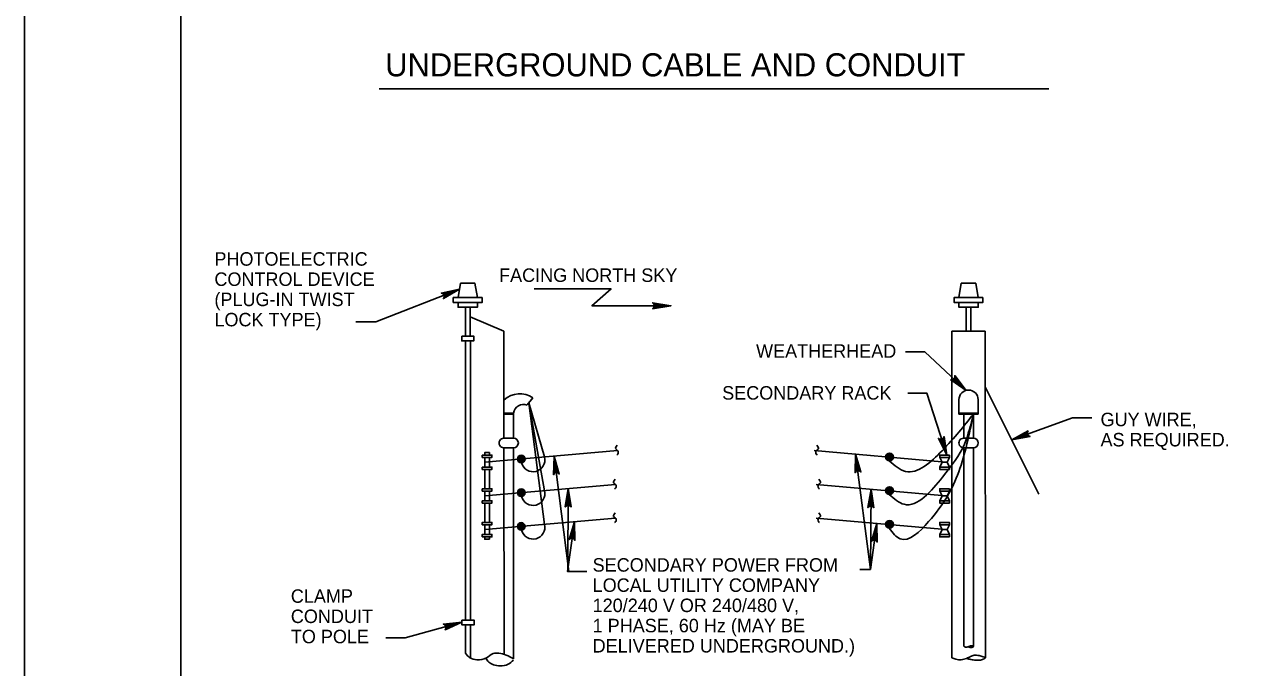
# Model space of a CAD drawing. Extents: x 638448 to 639352, y 297825 to 299013.
# Drawn here: x 638447.7 to 638752, y 298691.2 to 298851.5 of the extents above; entities that cross this region are included whole.
import ezdxf

# ---------------------------------------------------------------- set-up
doc = ezdxf.new("R2010")
doc.units = 0
for name, color, linetype in [('1', 7, 'Continuous'), ('2', 7, 'Continuous'), ('3', 7, 'Continuous'), ('PLT-BNDY', 7, 'Continuous')]:
    doc.layers.add(name, color=color, linetype=linetype)

msp = doc.modelspace()

# ---------------------------------------------------------------- linework, layer by layer
at = {"layer": '1'}
msp.add_lwpolyline([(639272.65, 298434.29), (639272.65, 298998.29), (638486.65, 298998.29), (638486.65, 298434.29), (639272.65, 298434.29), (639272.65, 298460.65), (639072.65, 298460.65), (639072.65, 298525.33), (639272.65, 298525.33), (639272.65, 298554.29), (639072.65, 298554.29), (639072.65, 298434.29), (639151.45, 298434.29), (639151.45, 298460.65), (639151.45, 298434.29), (639228.45, 298434.29), (639228.45, 298460.65), (639228.45, 298448.33), (639272.65, 298448.33)], dxfattribs=at)
at = {"layer": '2'}
for p, q in [((638535.24, 298777.34), (638556.11, 298785.48)), ((638530.28, 298777.34), (638535.24, 298777.34)), ((638567.16, 298774.99), (638558.76, 298778.59)), ((638567.16, 298774.99), (638567.17, 298748.35)), ((638687.16, 298774.99), (638678.82, 298774.99)), ((638687.16, 298774.99), (638687.2, 298693.57)), ((638687.17, 298761.18), (638700.53, 298734.39)), ((638572.95, 298756.62), (638574.38, 298758.44)), ((638680.59, 298754.35), (638680.59, 298757.95)), ((638685.39, 298754.35), (638685.39, 298757.95)), ((638577.31, 298743.66), (638573.36, 298757.14)), ((638577.31, 298735.26), (638573.36, 298757.14)), ((638573.36, 298757.14), (638577.31, 298726.86)), ((638569.57, 298754.59), (638567.17, 298754.59)), ((638569.57, 298754.35), (638567.17, 298754.35)), ((638569.57, 298754.59), (638569.57, 298748.35)), ((638685.39, 298754.59), (638680.59, 298754.59)), ((638685.39, 298754.35), (638680.59, 298754.35)), ((638681.79, 298754.35), (638681.79, 298748.35)), ((638684.19, 298754.35), (638684.19, 298748.35)), ((638569.57, 298748.35), (638567.17, 298748.35)), ((638569.57, 298745.95), (638567.17, 298745.95)), ((638567.18, 298745.95), (638567.18, 298745.95)), ((638567.18, 298745.95), (638567.2, 298694.36)), ((638569.58, 298745.95), (638569.6, 298693.31)), ((638684.19, 298748.35), (638681.79, 298748.35)), ((638684.19, 298745.95), (638681.79, 298745.95)), ((638681.8, 298745.95), (638681.82, 298696.48)), ((638684.2, 298745.95), (638684.22, 298696.48)), ((638687.18, 298745.95), (638687.18, 298745.95)), ((638562.38, 298742.35), (638595.49, 298745.25)), ((638563.58, 298744.75), (638563.58, 298744.75)), ((638571.46, 298742.37), (638570.7, 298743.18)), ((638570.7, 298743.18), (638571.96, 298742.41)), ((638572.11, 298743.35), (638570.72, 298742.96)), ((638570.72, 298742.96), (638572.29, 298743.15)), ((638571.83, 298743.78), (638570.76, 298743.31)), ((638570.76, 298743.31), (638572.11, 298743.35)), ((638570.93, 298743.7), (638571.83, 298743.78)), ((638572.29, 298743.15), (638570.93, 298742.6)), ((638570.93, 298742.6), (638572.22, 298742.74)), ((638571.96, 298742.41), (638571.28, 298743.93)), ((638571.28, 298743.93), (638572.33, 298742.99)), ((638572.22, 298742.74), (638571.46, 298742.37)), ((638571.5, 298743.15), (638571.5, 298743.15)), ((638572.33, 298742.99), (638571.96, 298743.89)), ((638676.37, 298742.46), (638644.5, 298745.25)), ((638663.51, 298744.44), (638662.47, 298743.5)), ((638662.47, 298743.5), (638662.83, 298744.4)), ((638664.07, 298743.46), (638662.5, 298743.66)), ((638662.5, 298743.66), (638663.87, 298743.11)), ((638663.87, 298743.11), (638662.57, 298743.25)), ((638662.57, 298743.25), (638663.34, 298742.87)), ((638664.04, 298743.81), (638662.68, 298743.86)), ((638662.68, 298743.86), (638664.07, 298743.46)), ((638662.83, 298742.92), (638663.51, 298744.44)), ((638664.09, 298743.68), (638662.83, 298742.92)), ((638663.87, 298744.21), (638662.97, 298744.28)), ((638662.97, 298744.28), (638664.04, 298743.81)), ((638663.29, 298743.66), (638663.29, 298743.66)), ((638663.34, 298742.87), (638664.09, 298743.68)), ((638675.82, 298743.55), (638676.42, 298742.35)), ((638677.62, 298742.35), (638678.22, 298743.55)), ((638676.42, 298742.35), (638675.82, 298741.15)), ((638676.42, 298742.35), (638677.62, 298742.35)), ((638678.22, 298741.15), (638677.62, 298742.35)), ((638562.38, 298733.95), (638594.97, 298736.8)), ((638676.37, 298734.06), (638645.02, 298736.8)), ((638571.46, 298733.97), (638570.7, 298734.78)), ((638570.7, 298734.78), (638571.96, 298734.01)), ((638572.11, 298734.95), (638570.72, 298734.56)), ((638570.72, 298734.56), (638572.29, 298734.75)), ((638571.83, 298735.38), (638570.76, 298734.91)), ((638570.76, 298734.91), (638572.11, 298734.95)), ((638570.93, 298735.3), (638571.83, 298735.38)), ((638572.29, 298734.75), (638570.93, 298734.2)), ((638570.93, 298734.2), (638572.22, 298734.34)), ((638571.96, 298734.01), (638571.28, 298735.53)), ((638571.28, 298735.53), (638572.33, 298734.59)), ((638572.22, 298734.34), (638571.46, 298733.97)), ((638571.5, 298734.75), (638571.5, 298734.75)), ((638572.33, 298734.59), (638571.96, 298735.49)), ((638663.51, 298736.04), (638662.47, 298735.1)), ((638662.47, 298735.1), (638662.83, 298736)), ((638664.07, 298735.06), (638662.5, 298735.26)), ((638662.5, 298735.26), (638663.87, 298734.71)), ((638663.87, 298734.71), (638662.57, 298734.85)), ((638662.57, 298734.85), (638663.34, 298734.47)), ((638664.04, 298735.41), (638662.68, 298735.46)), ((638662.68, 298735.46), (638664.07, 298735.06)), ((638662.83, 298734.52), (638663.51, 298736.04)), ((638664.09, 298735.28), (638662.83, 298734.52)), ((638663.87, 298735.81), (638662.97, 298735.88)), ((638662.97, 298735.88), (638664.04, 298735.41)), ((638663.29, 298735.26), (638663.29, 298735.26)), ((638663.34, 298734.47), (638664.09, 298735.28)), ((638675.82, 298735.15), (638676.42, 298733.95)), ((638676.42, 298733.95), (638675.82, 298732.75)), ((638676.42, 298733.95), (638677.62, 298733.95)), ((638677.62, 298733.95), (638678.22, 298735.15)), ((638678.22, 298732.75), (638677.62, 298733.95)), ((638562.38, 298725.55), (638594.97, 298728.4)), ((638676.37, 298725.66), (638645.02, 298728.4)), ((638663.51, 298727.64), (638662.47, 298726.7)), ((638662.47, 298726.7), (638662.83, 298727.6)), ((638662.83, 298726.12), (638663.51, 298727.64)), ((638663.87, 298727.41), (638662.97, 298727.48)), ((638662.97, 298727.48), (638664.04, 298727.01)), ((638571.46, 298725.57), (638570.7, 298726.38)), ((638570.7, 298726.38), (638571.96, 298725.61)), ((638572.11, 298726.55), (638570.72, 298726.16)), ((638570.72, 298726.16), (638572.29, 298726.35)), ((638571.83, 298726.98), (638570.76, 298726.51)), ((638570.76, 298726.51), (638572.11, 298726.55)), ((638570.93, 298726.9), (638571.83, 298726.98)), ((638572.29, 298726.35), (638570.93, 298725.8)), ((638570.93, 298725.8), (638572.22, 298725.94)), ((638571.96, 298725.61), (638571.28, 298727.13)), ((638571.28, 298727.13), (638572.33, 298726.19)), ((638572.22, 298725.94), (638571.46, 298725.57)), ((638571.5, 298726.35), (638571.5, 298726.35)), ((638572.33, 298726.19), (638571.96, 298727.09)), ((638664.07, 298726.66), (638662.5, 298726.86)), ((638662.5, 298726.86), (638663.87, 298726.31)), ((638663.87, 298726.31), (638662.57, 298726.45)), ((638662.57, 298726.45), (638663.34, 298726.07)), ((638664.04, 298727.01), (638662.68, 298727.06)), ((638662.68, 298727.06), (638664.07, 298726.66)), ((638664.09, 298726.88), (638662.83, 298726.12)), ((638663.29, 298726.86), (638663.29, 298726.86)), ((638663.34, 298726.07), (638664.09, 298726.88)), ((638675.82, 298726.75), (638676.42, 298725.55)), ((638676.42, 298725.55), (638675.82, 298724.35)), ((638676.42, 298725.55), (638677.62, 298725.55)), ((638677.62, 298725.55), (638678.22, 298726.75)), ((638678.22, 298724.35), (638677.62, 298725.55)), ((638563.58, 298723.15), (638563.58, 298723.15))]:
    msp.add_line(p, q, dxfattribs=at)
for points in [[(638551.85, 298784.41), (638552.11, 298784.18), (638556.11, 298785.48), (638551.85, 298784.41), (638551.57, 298784.51), (638556.11, 298785.48), (638552.28, 298783.77), (638552.25, 298783.42), (638556.11, 298785.48), (638552.1, 298783.14), (638552.25, 298783.42)], [(638555.76, 298783.39), (638556.36, 298786.99), (638559.96, 298786.99), (638560.56, 298783.39), (638561.76, 298783.39)], [(638608.81, 298781.36), (638589.1, 298781.36), (638593.88, 298785.56), (638584.28, 298785.56), (638574.68, 298785.56)], [(638680.59, 298783.39), (638681.19, 298786.99), (638684.79, 298786.99), (638685.39, 298783.39), (638686.59, 298783.39)], [(638604.45, 298781.91), (638604.61, 298781.59), (638608.81, 298781.36), (638604.45, 298781.91), (638604.22, 298782.1), (638608.81, 298781.36), (638604.61, 298781.15), (638604.46, 298780.84), (638608.81, 298781.36), (638604.22, 298780.63), (638604.46, 298780.84)], [(638682.39, 298774.94), (638682.39, 298780.99), (638683.59, 298780.99)], [(638683.59, 298780.99), (638683.59, 298774.99)], [(638678.82, 298774.99), (638678.82, 298693.57)], [(638667.26, 298769.89), (638672.06, 298769.89), (638682.39, 298760.27)], [(638679.57, 298763.65), (638679.48, 298763.3), (638682.39, 298760.27), (638679.57, 298763.65), (638679.54, 298763.94), (638682.39, 298760.27), (638679.18, 298762.98), (638678.85, 298762.86), (638682.39, 298760.27), (638678.54, 298762.86), (638678.85, 298762.86)], [(638667.82, 298759.55), (638672.62, 298759.55), (638677.61, 298744.15)], [(638713.68, 298753.39), (638708.88, 298753.39), (638693.78, 298747.91)], [(638698.07, 298748.89), (638697.81, 298749.13), (638693.78, 298747.91), (638698.07, 298748.89), (638698.34, 298748.78), (638693.78, 298747.91), (638697.65, 298749.54), (638697.69, 298749.89), (638693.78, 298747.91), (638697.84, 298750.16), (638697.69, 298749.89)], [(638676.78, 298748.47), (638676.53, 298748.22), (638677.61, 298744.15), (638676.78, 298748.47), (638676.9, 298748.74), (638677.61, 298744.15), (638676.12, 298748.08), (638675.77, 298748.13), (638677.61, 298744.15), (638675.5, 298748.29), (638675.77, 298748.13)], [(638579.68, 298739.47), (638579.97, 298739.67), (638579.67, 298743.87), (638579.68, 298739.47), (638579.52, 298739.23), (638579.67, 298743.87), (638580.41, 298739.73), (638580.74, 298739.62), (638579.67, 298743.87), (638580.98, 298739.41), (638580.74, 298739.62)], [(638583.35, 298715.08), (638579.67, 298743.87)], [(638654.86, 298739.98), (638655.15, 298740.18), (638654.85, 298744.38), (638654.86, 298739.98), (638654.7, 298739.74), (638654.85, 298744.38), (638655.59, 298740.24), (638655.92, 298740.13), (638654.85, 298744.38), (638656.15, 298739.92), (638655.92, 298740.13)], [(638658.53, 298715.59), (638654.85, 298744.38)], [(638582.65, 298731.42), (638582.97, 298731.58), (638583.23, 298735.78), (638582.65, 298731.42), (638582.46, 298731.2), (638583.23, 298735.78), (638583.41, 298731.58), (638583.72, 298731.43), (638583.23, 298735.78), (638583.93, 298731.19), (638583.72, 298731.43)], [(638583.08, 298715.08), (638583.23, 298735.78)], [(638658.1, 298731.26), (638658.42, 298731.42), (638658.68, 298735.61), (638658.1, 298731.26), (638657.91, 298731.03), (638658.68, 298735.61), (638658.86, 298731.42), (638659.17, 298731.26), (638658.68, 298735.61), (638659.38, 298731.02), (638659.17, 298731.26)], [(638658.53, 298715.59), (638658.68, 298735.61)], [(638587.83, 298715.08), (638583.03, 298715.08), (638584.79, 298727.51)], [(638583.64, 298723.27), (638583.97, 298723.39), (638584.79, 298727.51), (638583.64, 298723.27), (638583.42, 298723.08), (638584.79, 298727.51), (638584.41, 298723.33), (638584.7, 298723.14), (638584.79, 298727.51), (638584.87, 298722.87), (638584.7, 298723.14)], [(638658.53, 298715.59), (638660.16, 298727.08)], [(638659.01, 298722.84), (638659.34, 298722.96), (638660.16, 298727.08), (638659.01, 298722.84), (638658.79, 298722.65), (638660.16, 298727.08), (638659.78, 298722.9), (638660.06, 298722.7), (638660.16, 298727.08), (638660.24, 298722.44), (638660.06, 298722.7)], [(638658.53, 298715.59), (638655.86, 298715.59)], [(638537.77, 298698.58), (638542.57, 298698.58), (638556.72, 298702.49)], [(638552.37, 298701.86), (638552.61, 298701.6), (638556.72, 298702.49), (638552.37, 298701.86), (638552.11, 298701.98), (638556.72, 298702.49), (638552.73, 298701.17), (638552.67, 298700.83), (638556.72, 298702.49), (638552.5, 298700.57), (638552.67, 298700.83)], [(638557.62, 298694.75), (638557.62, 298701.79), (638558.82, 298701.79), (638558.82, 298693.6)]]:
    msp.add_lwpolyline(points, dxfattribs=at)
for points in [[(638561.76, 298783.39), (638561.76, 298782.19), (638554.56, 298782.19), (638554.56, 298783.39)], [(638686.59, 298783.39), (638686.59, 298782.19), (638679.39, 298782.19), (638679.39, 298783.39)], [(638555.76, 298782.19), (638555.76, 298780.99), (638560.56, 298780.99), (638560.56, 298782.19)], [(638558.76, 298780.99), (638558.76, 298773.79), (638557.56, 298773.79), (638557.56, 298780.99)], [(638680.59, 298782.19), (638680.59, 298780.99), (638685.39, 298780.99), (638685.39, 298782.19)], [(638556.66, 298773.79), (638556.66, 298772.59), (638559.66, 298772.59), (638559.66, 298773.79)], [(638558.82, 298772.59), (638558.82, 298702.99), (638557.62, 298702.99), (638557.62, 298772.59)], [(638561.78, 298744.15), (638561.78, 298743.55), (638564.18, 298743.55), (638564.18, 298744.15)], [(638563.58, 298744.75), (638563.58, 298744.15), (638562.38, 298744.15), (638562.38, 298744.75)], [(638563.58, 298743.55), (638563.58, 298741.15), (638562.38, 298741.15), (638562.38, 298743.55)], [(638678.22, 298744.15), (638678.22, 298743.55), (638675.82, 298743.55), (638675.82, 298744.15)], [(638561.78, 298741.15), (638561.78, 298740.55), (638564.18, 298740.55), (638564.18, 298741.15)], [(638563.58, 298740.55), (638563.58, 298735.75), (638562.38, 298735.75), (638562.38, 298740.55)], [(638678.22, 298741.15), (638678.22, 298740.55), (638675.82, 298740.55), (638675.82, 298741.15)], [(638561.78, 298735.75), (638561.78, 298735.15), (638564.18, 298735.15), (638564.18, 298735.75)], [(638563.58, 298735.15), (638563.58, 298732.75), (638562.38, 298732.75), (638562.38, 298735.15)], [(638678.22, 298735.75), (638678.22, 298735.15), (638675.82, 298735.15), (638675.82, 298735.75)], [(638561.78, 298732.75), (638561.78, 298732.15), (638564.18, 298732.15), (638564.18, 298732.75)], [(638563.58, 298732.15), (638563.58, 298727.35), (638562.38, 298727.35), (638562.38, 298732.15)], [(638678.22, 298732.75), (638678.22, 298732.15), (638675.82, 298732.15), (638675.82, 298732.75)], [(638561.78, 298726.75), (638561.78, 298727.35), (638564.18, 298727.35), (638564.18, 298726.75)], [(638563.58, 298724.35), (638563.58, 298726.75), (638562.38, 298726.75), (638562.38, 298724.35)], [(638678.22, 298726.75), (638678.22, 298727.35), (638675.82, 298727.35), (638675.82, 298726.75)], [(638561.78, 298723.75), (638561.78, 298724.35), (638564.18, 298724.35), (638564.18, 298723.75)], [(638563.58, 298723.15), (638563.58, 298723.75), (638562.38, 298723.75), (638562.38, 298723.15)], [(638678.22, 298723.75), (638678.22, 298724.35), (638675.82, 298724.35), (638675.82, 298723.75)], [(638556.72, 298702.99), (638556.72, 298701.79), (638559.72, 298701.79), (638559.72, 298702.99)]]:
    msp.add_lwpolyline(points, close=True, dxfattribs=at)
for centre in [(638571.5, 298743.15), (638663.29, 298743.66), (638571.5, 298734.75), (638663.29, 298735.26), (638663.29, 298726.86), (638571.5, 298726.35)]:
    msp.add_circle(centre, 0.96, dxfattribs=at)
for centre, radius, start, end in [((638571.15, 298753.47), 5.93, 56.9427, 131.3756), ((638682.99, 298757.95), 2.4, 0, 180), ((638572.07, 298754.25), 2.52, 69.6112, 172.2289), ((638567.17, 298747.15), 1.2, 90, 270.1833), ((638569.57, 298747.15), 1.2, 270, 90), ((638681.79, 298747.15), 1.2, 90, 270.1833), ((638684.19, 298747.15), 1.2, 270, 90), ((638574.45, 298742.93), 2.95, 194.3606, 14.3606), ((638574.45, 298734.53), 2.95, 194.3606, 14.3606), ((638574.45, 298726.13), 2.95, 194.3606, 14.3606)]:
    msp.add_arc(centre, radius, start, end, dxfattribs=at)
for points in [[(638684.19, 298754.35), (638676.39, 298745.2), (638667.26, 298740.07), (638663.21, 298742.7)], [(638684.19, 298754.35), (638681.95, 298746.87), (638676.5, 298738.66), (638666.94, 298731.86), (638663.21, 298734.3)], [(638684.19, 298754.35), (638680.55, 298739.96), (638673.04, 298727.54), (638665.97, 298723.22), (638663.21, 298725.9)], [(638595.44, 298746.61), (638595.05, 298745.7), (638595.57, 298745.18), (638595.57, 298744.4), (638595.31, 298744.14)], [(638645.16, 298746.61), (638645.55, 298745.7), (638645.03, 298745.18), (638645.03, 298744.4), (638645.29, 298744.14)], [(638594.91, 298738.16), (638594.52, 298737.25), (638595.04, 298736.73), (638595.04, 298735.95), (638594.78, 298735.69)], [(638645.68, 298738.16), (638646.07, 298737.25), (638645.55, 298736.73), (638645.55, 298735.95), (638645.81, 298735.69)], [(638594.91, 298729.76), (638594.52, 298728.85), (638595.04, 298728.33), (638595.04, 298727.55), (638594.78, 298727.29)], [(638645.68, 298729.76), (638646.07, 298728.85), (638645.55, 298728.33), (638645.55, 298727.55), (638645.81, 298727.29)], [(638557.62, 298694.75), (638558.71, 298693.6), (638560.43, 298693.12), (638562.83, 298693.6), (638564.46, 298694.65), (638565.9, 298694.75), (638567.72, 298694.27), (638569.6, 298693.31)], [(638678.82, 298693.57), (638679.82, 298693.23), (638681.18, 298693.11), (638682.44, 298693.46), (638683.47, 298693.89), (638684.38, 298694.21), (638685.61, 298694.14), (638686.67, 298693.84), (638687.2, 298693.57)], [(638681.82, 298696.48), (638682.24, 298696.28), (638682.82, 298696.31), (638683.27, 298696.46), (638683.67, 298696.61), (638684.22, 298696.48)], [(638684.22, 298696.48), (638684.05, 298696.23), (638683.6, 298696.18), (638683.14, 298696.23), (638682.99, 298696.31)], [(638569.6, 298693.02), (638568.2, 298691.97), (638566.28, 298691.58), (638564.56, 298691.87), (638563.4, 298692.54), (638562.64, 298693.5)], [(638687.2, 298693.57), (638686.49, 298693.18), (638685.36, 298692.98), (638684.13, 298693.08), (638683.07, 298693.28), (638682.61, 298693.43)]]:
    msp.add_spline(points, degree=3, dxfattribs=at)
at = {"layer": '3'}
msp.add_line((638536.07, 298835.46), (638702.97, 298835.46), dxfattribs=at)
at = {"layer": 'PLT-BNDY'}
msp.add_lwpolyline([(638447.65, 299013.29), (639288.65, 299013.29), (639288.65, 298419.29), (638447.65, 298419.29)], close=True, dxfattribs=at)

# ---------------------------------------------------------------- texts
at = {"layer": '3'}
for s, height, p in [('UNDERGROUND CABLE AND CONDUIT', 5.76, (638537.59, 298838.55)), ('PHOTOELECTRIC', 3.36, (638495.01, 298791.35)), ('CONTROL DEVICE', 3.36, (638495.01, 298786.31)), ('FACING NORTH SKY', 3.36, (638565.97, 298787.31)), ('(PLUG-IN TWIST', 3.36, (638495.01, 298781.27)), ('LOCK TYPE)', 3.36, (638495.01, 298776.23)), ('WEATHERHEAD', 3.36, (638630.03, 298768.4)), ('SECONDARY RACK', 3.36, (638621.58, 298757.96)), ('GUY WIRE,', 3.36, (638715.89, 298751.33)), ('AS REQUIRED.', 3.36, (638715.89, 298746.29)), ('SECONDARY POWER FROM', 3.36, (638589.29, 298715.07)), ('LOCAL UTILITY COMPANY', 3.36, (638589.29, 298710.03)), ('CLAMP', 3.36, (638514.06, 298707.3)), ('120/240 V OR 240/480 V, ', 3.36, (638589.29, 298704.99)), ('CONDUIT', 3.36, (638514.06, 298702.26)), ('1 PHASE, 60 Hz (MAY BE ', 3.36, (638589.29, 298699.95)), ('TO POLE', 3.36, (638514.06, 298697.22)), ('DELIVERED UNDERGROUND.)', 3.36, (638589.29, 298694.91))]:
    msp.add_text(s, height=height, dxfattribs=at).set_placement(p)

doc.saveas('drawing.dxf')
